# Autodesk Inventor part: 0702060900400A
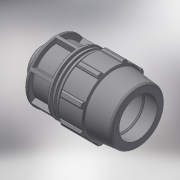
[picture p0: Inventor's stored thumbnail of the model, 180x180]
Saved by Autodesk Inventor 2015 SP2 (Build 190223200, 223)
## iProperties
Created: 2017-02
Part Number: 0702060900400A
Material: Generic
Description: PLASSON MALE ADAPTOR 90-4"
Document SubType Name: Modeling
Designer: KIM
Mass: 964.158 g
Surface Area: 1468.9 cm^2
Volume: 964.158 cm^3
Density: 1 g/cm^3
Appearance: Default
Author: KIM
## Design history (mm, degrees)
derived "87020.ipt"
feature "Solid1::87020.ipt"
tag "TaggingFeature1"
body "Solid1"
other parameters: "d4" = 34.14286, "d5" = 59.75, "d7" = 152, "d8" = 114, "d9" = 34.14286, "d11" = 6.82857, "d12" = 121.6, "d13" = 120 deg, "d14" = 117, "d15" = 6 deg, "d16" = 136.8, "d18" = 4.5, "d19" = 35 deg, "d20" = 17.5 deg, "d21" = 141.36, "d23" = 0, "d25" = 360 deg, "d27" = 3.04, "d34" = 7.6, "d36" = 0, "d42" = 64.53, "d43" = 4.56, "d46" = 2.7, "d51" = 239, "d53" = 1.8, "d55" = 360 deg, "d57" = 113.03, "d58" = 79.121, "d59" = 47.8, "d61" = 134.064, "d62" = 2.65257, "d63" = 2.65257, "d66" = 5.30514, "E_" = 152, "H_" = 239, "R_" = 113.03, "d60" = 13.26286
